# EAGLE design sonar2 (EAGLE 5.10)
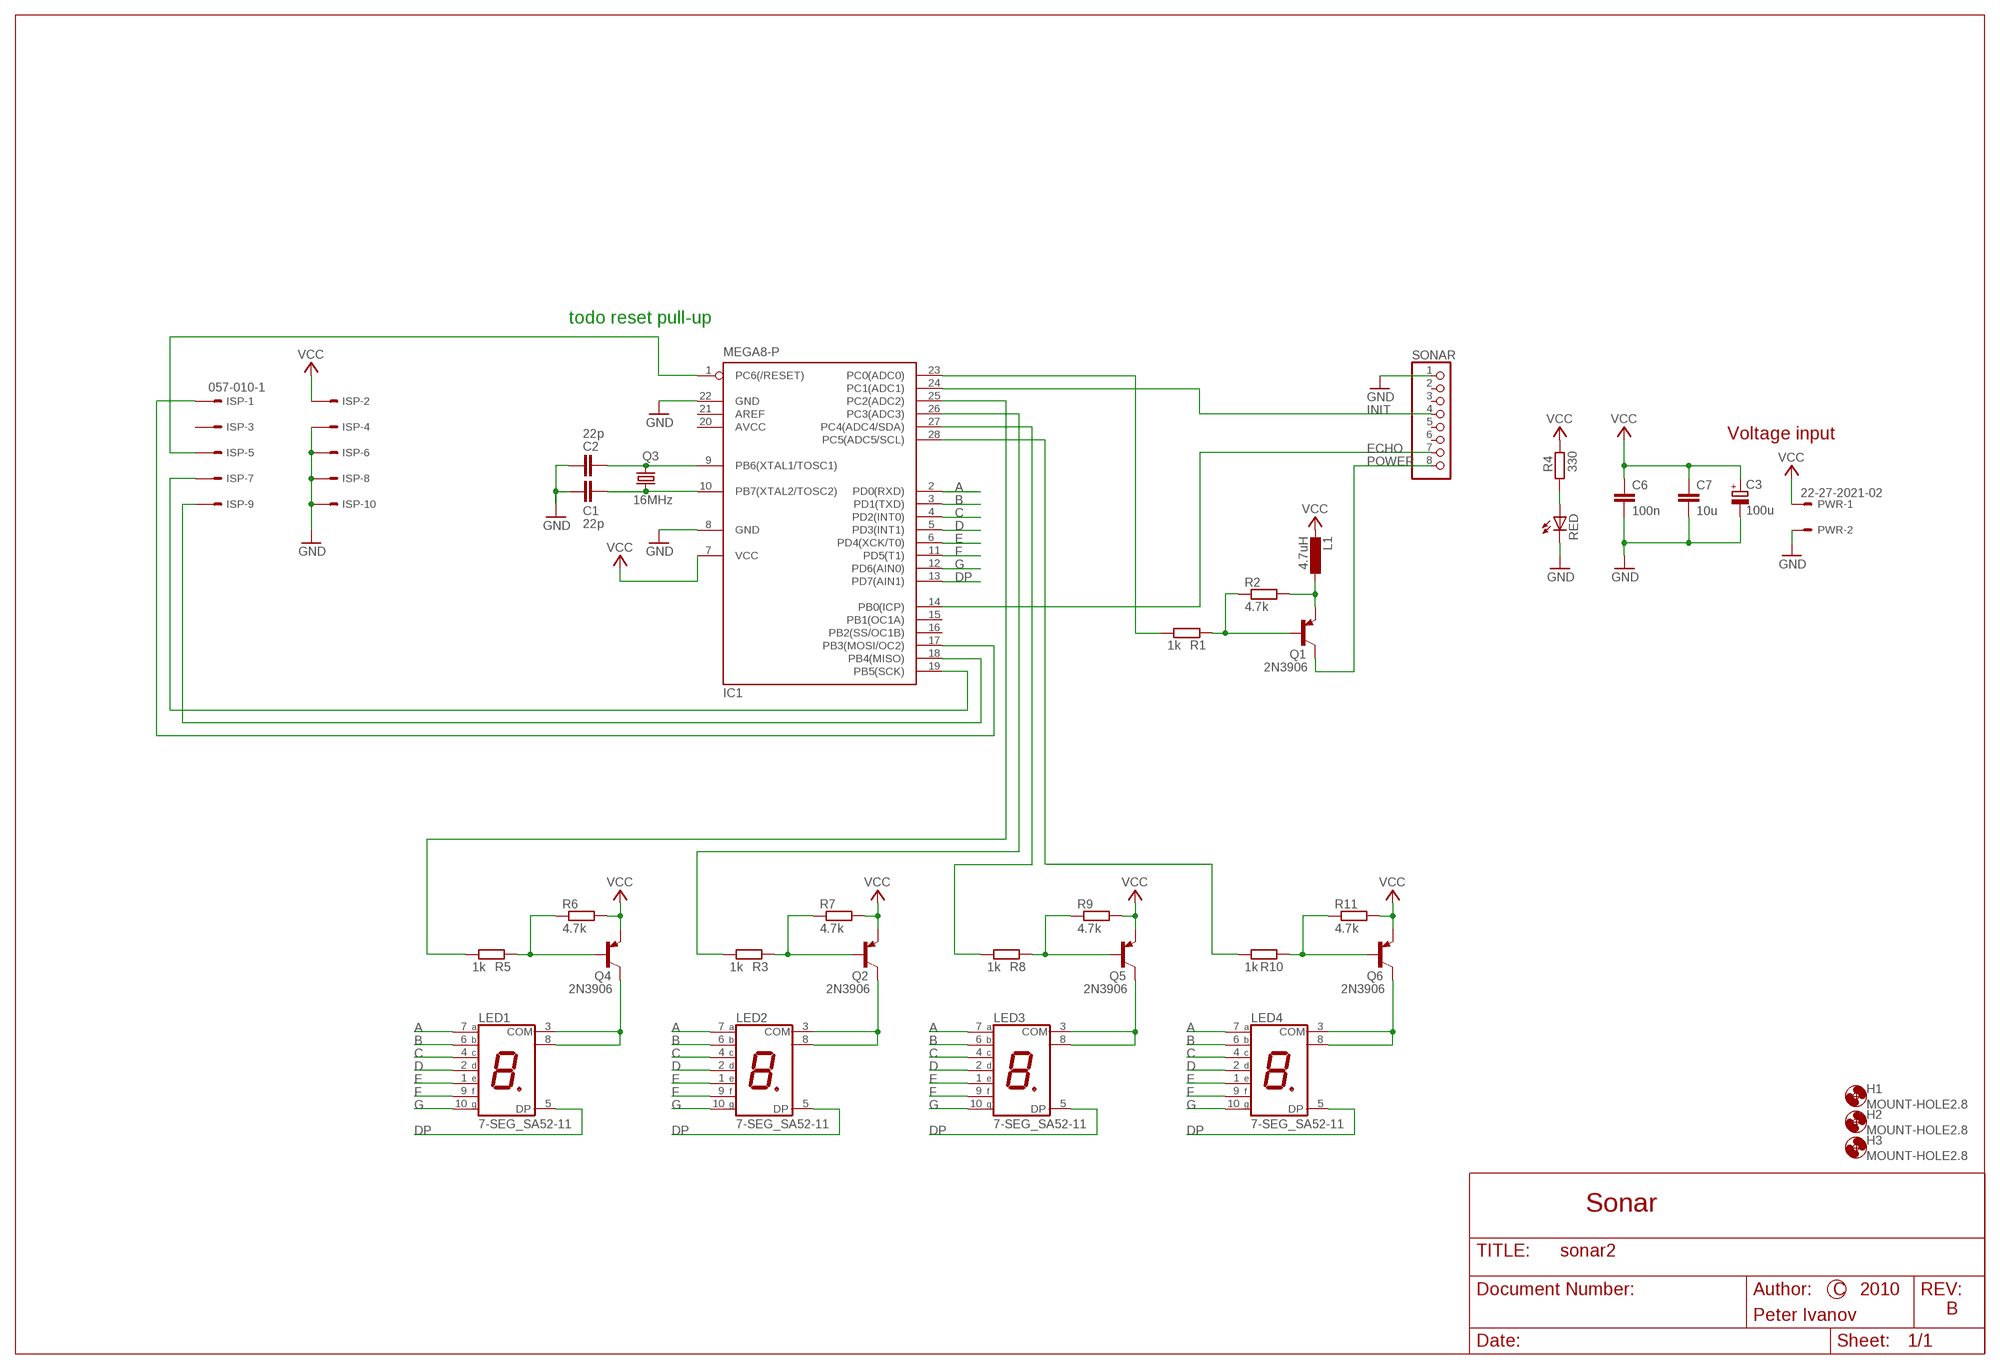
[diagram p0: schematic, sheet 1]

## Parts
C1  22p  C-EUC0805  [C0805]
C2  22p  C-EUC0805  [C0805]
C3  100u  CPOL-EUE2-5  [E2-5]
C6  100n  C-EUC0805  [C0805]
C7  10u  C-EUC1210  [C1210]
H1  MOUNT-HOLE2.8  [2,8]
H2  MOUNT-HOLE2.8  [2,8]
H3  MOUNT-HOLE2.8  [2,8]
IC1  MEGA8-P  [DIL28-3]
ISP  057-010-1  [057-010-1]
L1  4.7uH  L-EUL3230M  [L3230M]
LED1  7-SEG_SA52-11  [SA52-11]
LED2  7-SEG_SA52-11  [SA52-11]
LED3  7-SEG_SA52-11  [SA52-11]
LED4  7-SEG_SA52-11  [SA52-11]
PWR  22-27-2021-02  [6410-02]
Q1  2N3906  [TO92]
Q2  2N3906  [TO92]
Q3  16MHz  CRYSTALHC49S  [HC49/S]
Q4  2N3906  [TO92]
Q5  2N3906  [TO92]
Q6  2N3906  [TO92]
R1  1k  R-EU_R0805  [R0805]
R2  4.7k  R-EU_R0805  [R0805]
R3  1k  R-EU_R0805  [R0805]
R4  330  R-EU_R0805  [R0805]
R5  1k  R-EU_R0805  [R0805]
R6  4.7k  R-EU_R0805  [R0805]
R7  4.7k  R-EU_R0805  [R0805]
R8  1k  R-EU_R0805  [R0805]
R9  4.7k  R-EU_R0805  [R0805]
R10  1k  R-EU_R0805  [R0805]
R11  4.7k  R-EU_R0805  [R0805]
RED  LED3MM  [LED3MM]
SONAR  PINHD-1X8  [1X08]

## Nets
A: IC1.2(PD0(RXD)) LED1.7(A) LED2.7(A) LED3.7(A) LED4.7(A)
B: IC1.3(PD1(TXD)) LED1.6(B) LED2.6(B) LED3.6(B) LED4.6(B)
C: IC1.4(PD2(INT0)) LED1.4(C) LED2.4(C) LED3.4(C) LED4.4(C)
D: IC1.5(PD3(INT1)) LED1.2(D) LED2.2(D) LED3.2(D) LED4.2(D)
DP: IC1.13(PD7(AIN1)) LED1.5(DP) LED2.5(DP) LED3.5(DP) LED4.5(DP)
E: IC1.6(PD4(XCK/T0)) LED1.1(E) LED2.1(E) LED3.1(E) LED4.1(E)
ECHO: IC1.14(PB0(ICP)) SONAR.7
F: IC1.11(PD5(T1)) LED1.9(F) LED2.9(F) LED3.9(F) LED4.9(F)
G: IC1.12(PD6(AIN0)) LED1.10(G) LED2.10(G) LED3.10(G) LED4.10(G)
GND: C1.1 C2.1 C3.- C6.2 C7.2 IC1.8(GND) IC1.22(GND) ISP.4 ISP.6 ISP.8 ISP.10 PWR.2 RED.K(C) SONAR.1
INIT: IC1.24(PC1(ADC1)) SONAR.4
N$1: Q1.2(B) R1.2 R2.1
N$2: L1.1 Q1.3(E) R2.2
N$3: IC1.23(PC0(ADC0)) R1.1
N$4: IC1.17(PB3(MOSI/OC2)) ISP.1
N$5: IC1.19(PB5(SCK)) ISP.7
N$6: IC1.1(PC6(/RESET)) ISP.5
N$7: IC1.18(PB4(MISO)) ISP.9
N$8: C2.2 IC1.9(PB6(XTAL1/TOSC1)) Q3.2
N$9: C1.2 IC1.10(PB7(XTAL2/TOSC2)) Q3.1
N$10: R4.1 RED.A
N$11: LED2.3(COM) LED2.8(COM) Q2.1(C)
N$12: Q2.2(B) R3.2 R7.1
N$13: LED1.3(COM) LED1.8(COM) Q4.1(C)
N$14: Q4.2(B) R5.2 R6.1
N$15: LED3.3(COM) LED3.8(COM) Q5.1(C)
N$16: Q5.2(B) R8.2 R9.1
N$17: LED4.3(COM) LED4.8(COM) Q6.1(C)
N$18: Q6.2(B) R10.2 R11.1
N$19: IC1.25(PC2(ADC2)) R5.1
N$20: IC1.26(PC3(ADC3)) R3.1
N$21: IC1.27(PC4(ADC4/SDA)) R8.1
N$22: IC1.28(PC5(ADC5/SCL)) R10.1
POWER: Q1.1(C) SONAR.8
VCC: C3.+ C6.1 C7.1 IC1.7(VCC) ISP.2 L1.2 PWR.1 Q2.3(E) Q4.3(E) Q5.3(E) Q6.3(E) R4.2 R6.2 R7.2 R9.2 R11.2
Unconnected: IC1.15(PB1(OC1A)) IC1.16(PB2(SS/OC1B)) IC1.21(AREF) ISP.3 SONAR.2 SONAR.3 SONAR.5 SONAR.6

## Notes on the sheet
- todo reset pull-up
- Voltage input
- Sonar
- Author: | C | 2010
- B
- Peter Ivanov

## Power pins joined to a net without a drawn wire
AVCC: IC1.20(AVCC)

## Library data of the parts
C1 C2 C6 C7 = rcl:C-EU: CAPACITOR, European symbol
C3 = rcl:CPOL-EU: POLARIZED CAPACITOR, European symbol
H1-H3 = holes:MOUNT-HOLE: MOUNTING HOLE with drill center marker
IC1 = atmel:MEGA8-P: MICROCONTROLLER 8 Kbytes FLASH, 1 kbytes SRAM, 512 bytes EEPROM, USART, 4-channel 10 bit ADC, 2-channel 8 bit ADC Pin compatible with Atmega48, ATMega88, ATMega168 Source: avr.lbr
ISP = con-panduit:057-010-: CONNECTOR 10-pin series 057 contact pc board low profile headers
L1 = rcl:L-EU: INDUCTOR, European symbol
LED1-LED4 = display-kingbright:7-SEG_: Kingbright 14.2mm (0.56 INCH) SINGLE DIGIT NUMERIC DUISPLAY Source: SA56-11EWA(Ver1189471036.pdf
PWR = con-molex:22-?-02: CONNECTOR
Q1 Q2 Q4-Q6 = transistor-pnp:2N3906: PNP Transistor
Q3 = crystal:CRYSTAL: CRYSTAL
R1-R11 = rcl:R-EU_: RESISTOR, European symbol
RED = led:LED: LED
SONAR = pinhead:PINHD-1X8: PIN HEADER

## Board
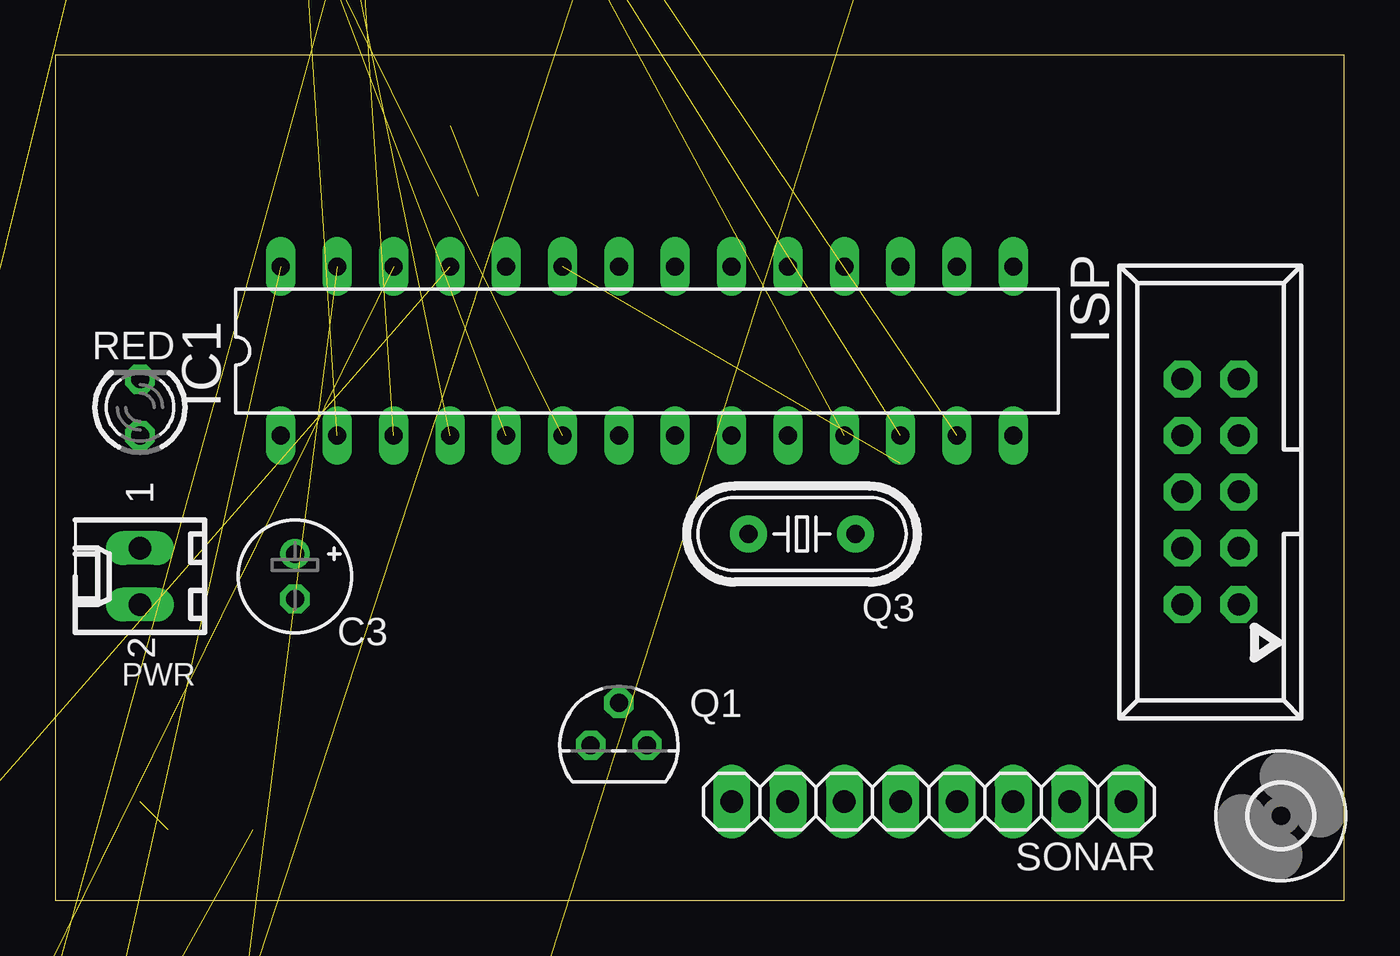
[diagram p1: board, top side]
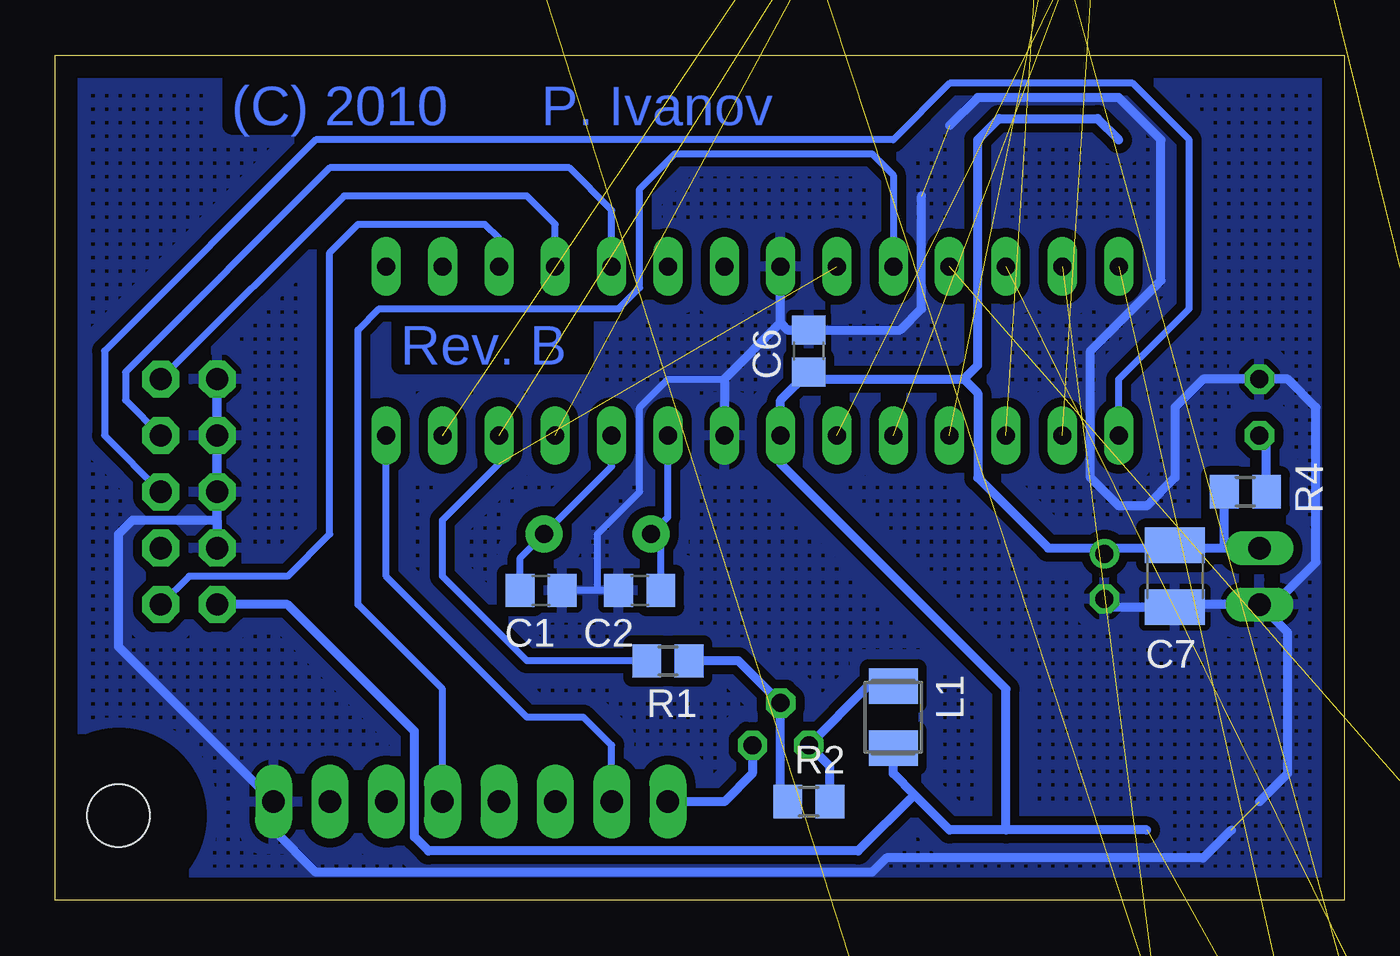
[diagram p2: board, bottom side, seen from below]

Size 58.09 x 38.09 mm. Coordinates in mm from the lower left corner, seen from the top.
Outline: 0,0 58.09,0 58.09,38.09 0,38.09 0,0
Copper layers (1*16): Top 0.035mm / dielectric 1.5mm / Bottom 0.035mm
Design rules "default": minimum track width 10mil, minimum drill 24mil, track to track 8mil, track to pad 8mil, pad to pad 8mil, via to via 8mil, smd to smd 8mil, copper to edge 40mil, drill to drill 8mil, minimum pad ring 10mil, minimum via ring 8mil, stop-mask expansion 4mil, vias tented up to drill 0mil, thermal gap 10mil

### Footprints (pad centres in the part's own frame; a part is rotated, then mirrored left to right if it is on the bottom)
C0805 = smd 1.3 x 1.5: 1 -0.95,0; 2 0.95,0
E2-5 = drill 0.813 pad 1.27 round: + -1.016,0 | drill 0.813 pad 1.27 octagon: - 1.016,0
C1210 = smd 1.6 x 2.7: 1 -1.4,0; 2 1.4,0
2,8 = hole 2.8: 0,0
DIL28-3 = drill 0.813 long: 1 -16.51,-3.81; 2 -13.97,-3.81; 3 -11.43,-3.81; 4 -8.89,-3.81; 5 -6.35,-3.81; 6 -3.81,-3.81; 7 -1.27,-3.81; 8 1.27,-3.81; 9 3.81,-3.81; 10 6.35,-3.81; 11 8.89,-3.81; 12 11.43,-3.81; 13 13.97,-3.81; 14 16.51,-3.81; 15 16.51,3.81; 16 13.97,3.81; 17 11.43,3.81; 18 8.89,3.81; 19 6.35,3.81; 20 3.81,3.81; 21 1.27,3.81; 22 -1.27,3.81; 23 -3.81,3.81; 24 -6.35,3.81; 25 -8.89,3.81; 26 -11.43,3.81; 27 -13.97,3.81; 28 -16.51,3.81
057-010-1 = drill 1 pad 1.67 octagon: 1 -5.08,-1.27; 2 -5.08,1.27; 3 -2.54,-1.27; 4 -2.54,1.27; 5 0,-1.27; 6 0,1.27; 7 2.54,-1.27; 8 2.54,1.27; 9 5.08,-1.27; 10 5.08,1.27
L3230M = smd 1.6 x 2.2: 1 -1.4,0; 2 1.4,0
SA52-11 = drill 0.8 round: 1 -5.08,-7.62; 2 -2.54,-7.62; 3 0,-7.62; 4 2.54,-7.62; 5 5.08,-7.62; 6 5.08,7.62; 7 2.54,7.62; 8 0,7.62; 9 -2.54,7.62; 10 -5.08,7.62
6410-02 = drill 1.016 long: 1 1.27,0; 2 -1.27,0
TO92 = drill 0.813 octagon: 1 1.27,0; 2 0,1.905; 3 -1.27,0
HC49/S = drill 0.8 pad 1.67 round: 1 -2.413,0; 2 2.413,0
R0805 = smd 1.3 x 1.5: 1 -0.95,0; 2 0.95,0
LED3MM = drill 0.813 octagon: A -1.27,0; K 1.27,0
1X08 = drill 1.016 pad 1.67 long: 1 -8.89,0; 2 -6.35,0; 3 -3.81,0; 4 -1.27,0; 5 1.27,0; 6 3.81,0; 7 6.35,0; 8 8.89,0

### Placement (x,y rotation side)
C1  36.2,13.97 180 bottom
C2  31.75,13.97 0 bottom
C3  10.79,14.61 270 top
C6  24.13,24.77 90 bottom
C7  7.62,14.61 270 bottom
H1  55.24,3.81 0 top
H2  not placed on the board
H3  not placed on the board
IC1  26.67,24.77 0 top
ISP  52.07,18.41 90 top
L1  20.32,8.26 270 bottom
LED1  not placed on the board
LED2  not placed on the board
LED3  not placed on the board
LED4  not placed on the board
PWR  3.81,14.61 90 top
Q1  25.4,6.99 0 top
Q2  not placed on the board
Q3  33.66,16.51 180 top
Q4  not placed on the board
Q5  not placed on the board
Q6  not placed on the board
R1  30.48,10.79 0 bottom
R2  24.13,4.45 0 bottom
R3  not placed on the board
R4  4.45,18.41 180 bottom
R5  not placed on the board
R6  not placed on the board
R7  not placed on the board
R8  not placed on the board
R9  not placed on the board
R10  not placed on the board
R11  not placed on the board
RED  3.81,22.23 90 top
SONAR  39.37,4.45 180 top

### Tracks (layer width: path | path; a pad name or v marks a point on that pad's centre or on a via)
A  (4 unrouted)
B  (4 unrouted)
C  (4 unrouted)
D  (4 unrouted)
DP  (4 unrouted)
E  (4 unrouted)
ECHO
  Bottom 0.305: SONAR.7 33.02,6.99 34.29,8.26 36.83,8.26 43.18,14.61 IC1.14
F  (4 unrouted)
G  (4 unrouted)
GND  (2 unrouted)
  Bottom 0.305: C2.1 33.66,13.97 | 33.66,13.97 C1.1 | 27.94,23.5 30.48,23.5 31.75,22.23 31.75,18.41 33.66,16.51 33.66,13.97
  Bottom 0.406: IC1.8 27.94,23.5 25.4,26.04 | 25.4,26.04 IC1.22 | C6.2 25.08,25.71 25.4,26.04 | 3.81,4.45 2.54,5.71 2.54,12.06 PWR.2 | PWR.2 7.49,13.34 C7.2 10.41,13.21 C3.- | ISP.10 ISP.8 ISP.6 50.8,17.14 | 50.8,17.14 ISP.4 | 50.8,17.14 54.61,17.14 55.24,16.51 55.24,11.43 SONAR.1 48.26,3.17 46.35,1.27 21.27,1.27 20.64,1.91 6.35,1.91 5.08,3.17 | PWR.2 3.17,13.34 1.27,15.24 1.27,22.23 2.54,23.5 RED.K 6.35,23.5 7.62,22.23 7.62,19.05 8.89,17.78 10.16,17.78 11.43,19.05 11.43,24.77 8.26,27.94 8.26,34.29 10.16,36.2 16.51,36.2 17.78,34.92 | C6.2 24.13,25.4 | 19.05,31.75 19.05,26.67 20,25.71 C6.2
  pour Bottom (isolate 0.406, hatched): 0,38.1 0,0 58.42,0 58.42,38.1
INIT
  Bottom 0.305: SONAR.4 40.64,9.53 44.45,13.34 44.45,25.72 43.5,26.67 32.7,26.67 31.75,27.62 31.75,32.07 30.16,33.66 21.27,33.66 20.32,32.7 IC1.24
N$1
  Bottom 0.305: R2.1 25.4,4.76
  Bottom 0.406: 25.4,4.76 Q1.2 27.3,10.79 R1.2
N$2
  Bottom 0.406: R2.2 23.18,6.04 Q1.3 21.46,9.65 L1.1
N$3  (1 unrouted)
  Bottom 0.305: R1.1 36.83,10.79 40.64,14.61 40.64,17.14 38.1,19.68
N$4
  Bottom 0.305: IC1.17 38.1,29.84 38.73,30.48 44.45,30.48 45.72,29.21 45.72,16.51 47.62,14.61 52.07,14.61 ISP.1
N$5
  Bottom 0.305: IC1.19 33.02,31.11 34.92,33.02 45.72,33.02 54.93,23.81 54.93,22.54 ISP.7
N$6
  Bottom 0.305: IC1.1 10.16,23.5 6.99,26.67 6.99,34.29 9.53,36.83 17.78,36.83 20.32,34.29 46.35,34.29 55.88,24.77 55.88,20.95 ISP.5
N$7
  Bottom 0.305: IC1.18 35.56,30.48 36.83,31.75 45.09,31.75 ISP.9
N$8
  Bottom 0.305: IC1.9 30.48,17.27 Q3.2 30.8,16.07 C2.2
N$9
  Bottom 0.305: IC1.10 33.02,19.56 Q3.1 37.15,15.43 C1.2
N$10
  Bottom 0.406: R4.1 3.5,20.64 RED.A
N$11  (2 unrouted)
N$12  (2 unrouted)
N$13  (2 unrouted)
N$14  (2 unrouted)
N$15  (2 unrouted)
N$16  (2 unrouted)
N$17  (2 unrouted)
N$18  (2 unrouted)
N$19  (1 unrouted)
N$20  (1 unrouted)
N$21  (1 unrouted)
N$22  (1 unrouted)
POWER
  Bottom 0.406: Q1.1 26.67,5.71 27.94,4.45 SONAR.8
VCC  (8 unrouted)
  Bottom 0.406: 8.89,3.17 15.24,3.17 | 15.24,3.17 17.78,3.17 19.37,4.76 | 19.37,4.76 20.32,5.71 L1.2 | 7.49,15.88 5.39,15.88 | 7.49,15.88 C7.1 | 10.79,15.88 13.34,15.88 16.51,19.05 16.51,22.86 17.14,23.5 | 10.79,15.88 7.49,15.88 | 17.14,23.5 23.81,23.5 C6.1 25.4,22.55 IC1.7 25.4,19.68 15.24,9.53 15.24,3.17 | ISP.2 47.62,13.34 41.91,7.62 41.91,2.86 41.27,2.22 21.91,2.22 19.37,4.76 | 5.39,15.88 R4.2 | 5.39,15.88 PWR.1 | 10.79,15.88 C3.+ | 17.14,23.5 16.51,24.13 16.51,34.29 15.56,35.24 11.11,35.24 10.16,34.29

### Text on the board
Bottom: P. Ivanov | (C) 2010 | Rev. B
